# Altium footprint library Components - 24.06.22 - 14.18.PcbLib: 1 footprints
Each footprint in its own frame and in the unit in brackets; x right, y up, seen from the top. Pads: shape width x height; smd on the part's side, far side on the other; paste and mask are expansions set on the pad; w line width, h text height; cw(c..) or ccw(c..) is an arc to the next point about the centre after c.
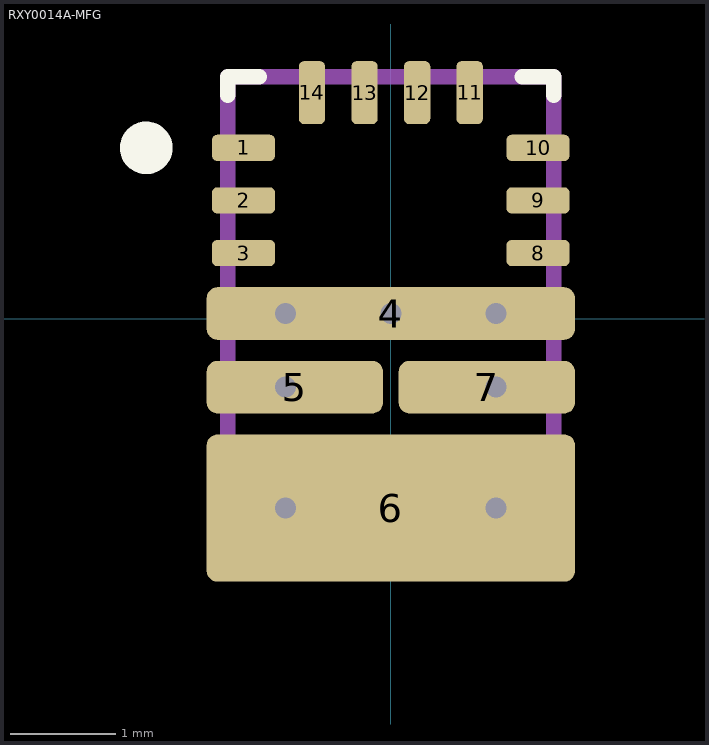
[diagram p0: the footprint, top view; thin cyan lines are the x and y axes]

## RXY0014A-MFG [mm]
pads (14):
  rrect40% 0.6x0.25 smd paste+0 mask-1000: 1(-1.4,1.625) 2(-1.4,1.125) 3(-1.4,0.625) 8(1.4,0.625) 9(1.4,1.125) 10(1.4,1.625)
  rrect40% 3.5x0.5 smd paste-1000 mask-1000: 4(0,0.05)
  rrect40% 1.675x0.5 smd paste-1000 mask-1000: 5(-0.913,-0.65) 7(0.913,-0.65)
  rrect14% 3.5x1.4 smd paste-1000 mask-1000: 6(0,-1.8)
  rrect40% 0.25x0.6 smd paste+0 mask-1000: 11(0.75,2.15) 12(0.25,2.15) 13(-0.25,2.15) 14(-0.75,2.15)
via 1,-1.8 diameter 0.5 hole 0.2
via -1,-1.8 diameter 0.5 hole 0.2
via 1,-0.65 diameter 0.5 hole 0.2
via -1,-0.65 diameter 0.5 hole 0.2
via 1,0.05 diameter 0.5 hole 0.2
via 0,0.05 diameter 0.5 hole 0.2
via -1,0.05 diameter 0.5 hole 0.2
Top Overlay:
  circle w0.25: c-2.325,1.625 r0.125
  lines w0.15: -1.55,2.125 -1.55,2.3 -1.25,2.3 ; 1.25,2.3 1.55,2.3 1.55,2.125
Top Paste:
  drawing of 10 lines, arcs and shapes, not listed
Top Solder:
  drawing of 14 lines, arcs and shapes, not listed
Mechanical 5:
  lines w0.15: -1.55,-2.3 -1.55,2.3 1.55,2.3 1.55,-2.3 -1.55,-2.3
  text ".Designator" at 0.05,0.192 h0.5
3D body "IC_DRV8243HQRXYRQ1_VQFN-HR14.STEP": height 0.25, standoff 0, extent -1.85,-2.6 1.85,2.55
